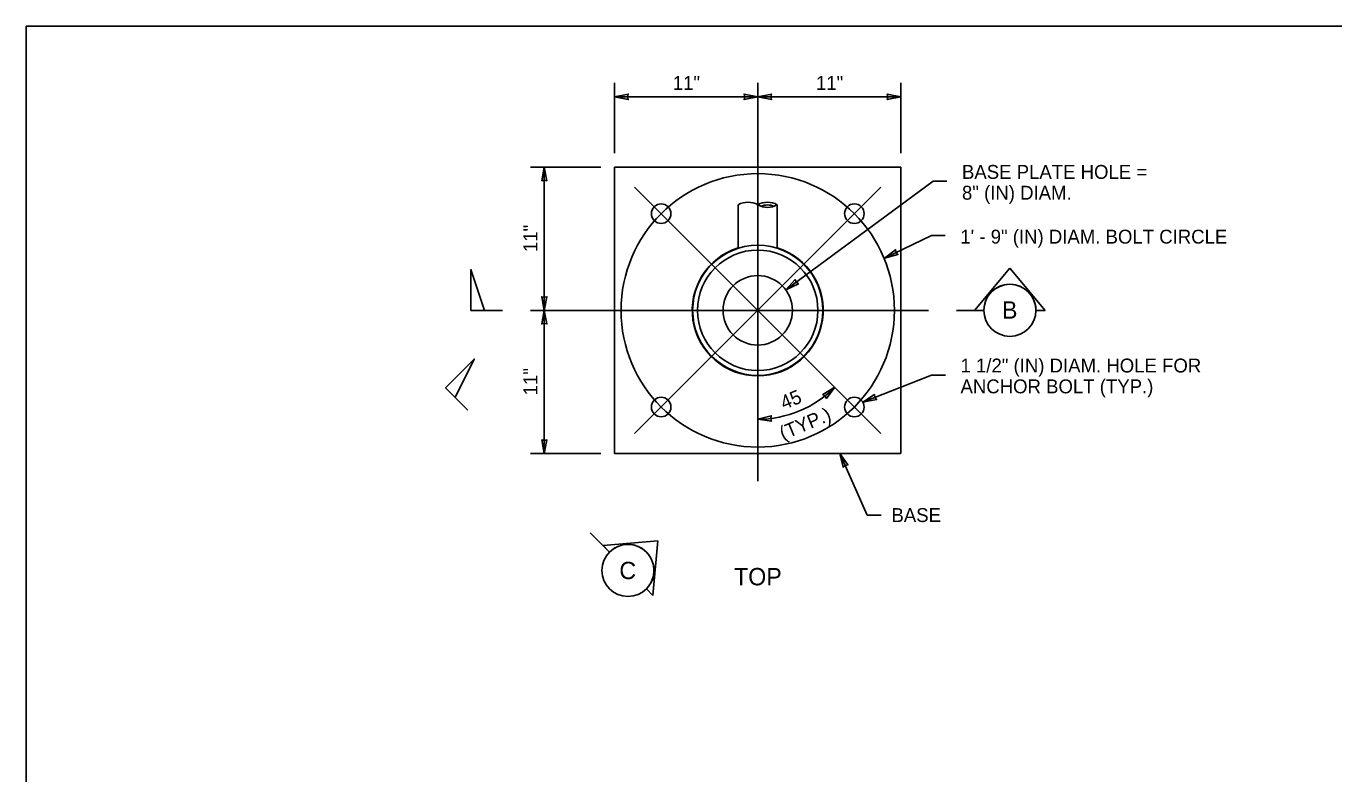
# Model space of a CAD drawing. Extents: x 99862 to 104211, y 98939 to 111076.
# Drawn here: x 100000 to 101507, y 110214 to 111075 of the extents above; entities that cross this region are included whole.
import ezdxf

# ---------------------------------------------------------------- set-up
doc = ezdxf.new("R2010")
doc.units = 0
for name, color, linetype in [('Level 11', 7, 'Continuous'), ('Level 15', 7, 'Continuous'), ('Level 20', 7, 'Continuous'), ('Level 60', 7, 'Continuous'), ('Level 7', 7, 'Continuous'), ('Level 9', 7, 'Continuous')]:
    doc.layers.add(name, color=color, linetype=linetype)

msp = doc.modelspace()

# ---------------------------------------------------------------- linework, layer by layer
at = {"layer": 'Level 11'}
for p, q in [((100820.7, 110869.2), (100820.7, 110819.2)), ((100865.7, 110819.2), (100865.7, 110869.2))]:
    msp.add_line(p, q, dxfattribs=at)
for centre, radius, start, end in [((100832, 110849.7), 22.5, 60, 120), ((100854.5, 110849.7), 22.5, 60, 120), ((100854.5, 110888.7), 22.5, 240, 300), ((100854.5, 110849.7), 19.3, 67.1582, 112.8418)]:
    msp.add_arc(centre, radius, start, end, dxfattribs=at)
at = {"layer": 'Level 15'}
for p, q in [((100678.2, 110928.6), (100678.2, 111009.6)), ((100843.2, 110550.6), (100843.2, 111009.6)), ((101008.2, 110928.6), (101008.2, 111009.6)), ((100843.2, 110993.6), (100678.2, 110993.6)), ((101008.2, 110993.6), (100843.2, 110993.6)), ((100662.2, 110912.6), (100581.2, 110912.6)), ((100597.2, 110912.6), (100597.2, 110747.6)), ((100985.2, 110605.7), (100701.3, 110889.6)), ((100701.3, 110605.7), (100985.2, 110889.6)), ((100875.5, 110771.3), (101045.3, 110896.3)), ((101045.3, 110896.3), (101061.3, 110896.3)), ((100989.3, 110807.7), (101043.4, 110833.7)), ((101043.4, 110833.7), (101059.4, 110833.7)), ((101040.2, 110747.6), (100581.2, 110747.6)), ((100597.2, 110747.6), (100597.2, 110582.6)), ((100964.3, 110641.9), (101043.6, 110673.1)), ((101043.6, 110673.1), (101059.6, 110673.1)), ((100662.2, 110582.6), (100581.2, 110582.6)), ((100937.8, 110582.7), (100969.3, 110511.7)), ((100969.3, 110511.7), (100985.3, 110511.7))]:
    msp.add_line(p, q, dxfattribs=at)
for points in [[(100678.2, 110993.6), (100694, 110990.5), (100693.2, 110993.6), (100694, 110996.7)], [(100843.2, 110993.6), (100827.5, 110990.5), (100828.2, 110993.6), (100827.5, 110996.7)], [(100843.2, 110993.6), (100859, 110990.5), (100858.2, 110993.6), (100859, 110996.7)], [(101008.2, 110993.6), (100992.5, 110990.5), (100993.2, 110993.6), (100992.5, 110996.7)], [(100597.2, 110912.6), (100594.2, 110896.9), (100597.2, 110897.6), (100600.3, 110896.9)], [(100989.3, 110807.7), (101004.7, 110811.9), (101002.7, 110814.3), (101002, 110817.4)], [(100875.5, 110771.3), (100890, 110778.1), (100887.6, 110780.2), (100886.3, 110783.1)], [(100597.2, 110747.6), (100594.2, 110763.3), (100597.2, 110762.6), (100600.3, 110763.3)], [(100597.2, 110747.6), (100594.2, 110731.9), (100597.2, 110732.6), (100600.3, 110731.9)], [(100932, 110658.9), (100922.3, 110646.1), (100920.8, 110648.9), (100918.2, 110650.7)], [(100964.3, 110641.9), (100980.1, 110644.8), (100978.3, 110647.4), (100977.8, 110650.5)], [(100843.2, 110622.1), (100859.1, 110620), (100858.2, 110623), (100858.7, 110626.1)], [(100597.2, 110582.6), (100594.2, 110598.3), (100597.2, 110597.6), (100600.3, 110598.3)], [(100937.8, 110582.7), (100941.5, 110567.1), (100944, 110569), (100947.1, 110569.6)]]:
    msp.add_lwpolyline(points, close=True, dxfattribs=at)
msp.add_circle((100843.2, 110747.6), 157.5, dxfattribs=at)
msp.add_arc((100843.2, 110747.6), 125.5, 270, 315, dxfattribs=at)
at = {"layer": 'Level 60'}
for p, q in [((100000, 111075), (100000, 109000)), ((103150, 111075), (100000, 111075))]:
    msp.add_line(p, q, dxfattribs=at)
at = {"layer": 'Level 7'}
for p, q in [((101008.2, 110912.6), (100678.2, 110912.6)), ((100678.2, 110912.6), (100678.2, 110582.6)), ((101008.2, 110582.6), (101008.2, 110912.6)), ((100678.2, 110582.6), (101008.2, 110582.6))]:
    msp.add_line(p, q, dxfattribs=at)
for centre, radius in [((100731.9, 110859), 11.3), ((100954.6, 110859), 11.3), ((100843.2, 110747.6), 75), ((100843.2, 110747.6), 69.4), ((100843.2, 110747.6), 40), ((100731.9, 110636.2), 11.3), ((100954.6, 110636.2), 11.3)]:
    msp.add_circle(centre, radius, dxfattribs=at)
msp.add_arc((100843.2, 110747.6), 75.5, 107.3457, 72.6543, dxfattribs=at)
at = {"layer": 'Level 9'}
for p, q in [((101133.8, 110796.1), (101093.2, 110747.6)), ((101174.4, 110747.6), (101133.8, 110796.1)), ((100549.2, 110747.6), (100512.7, 110747.6)), ((101102.2, 110747.6), (101072.2, 110747.6)), ((101093.2, 110747.6), (101103.8, 110747.6)), ((101163.8, 110747.6), (101174.4, 110747.6)), ((100509.2, 110632.4), (100483.4, 110658.2)), ((100671.3, 110470.2), (100650.1, 110491.4)), ((100727.9, 110482.2), (100664.9, 110476.6)), ((100722.4, 110419.2), (100727.9, 110482.2)), ((100664.9, 110476.6), (100672.4, 110469.1)), ((100714.9, 110426.7), (100722.4, 110419.2))]:
    msp.add_line(p, q, dxfattribs=at)
for points in [[(100528.2, 110747.6), (100512.7, 110794.5), (100512.7, 110747.6)], [(100494.3, 110647.2), (100516.5, 110691.4), (100483.4, 110658.2)]]:
    msp.add_lwpolyline(points, close=True, dxfattribs=at)
for centre in [(101133.8, 110747.6), (100693.6, 110447.9)]:
    msp.add_circle(centre, 30, dxfattribs=at)
for centre, start, end in [((101133.8, 110747.6), 359.9978, 180.0022), ((100693.6, 110447.9), 314.9978, 135.0022)]:
    msp.add_arc(centre, 30, start, end, dxfattribs=at)

# ---------------------------------------------------------------- texts
at = {"layer": 'Level 15'}
for s, p in [('11"', (100745.3, 111001.6)), ('11"', (100910.3, 111001.6)), ('BASE PLATE HOLE = ', (101078.6, 110899.1)), ('8" (IN) DIAM.', (101078.6, 110875.1)), ('1\' - 9" (IN) DIAM. BOLT CIRCLE', (101076.7, 110824.5)), ('1 1/2" (IN) DIAM. HOLE FOR', (101076.9, 110676)), ('ANCHOR BOLT (TYP.)', (101076.9, 110652))]:
    msp.add_text(s, height=16, dxfattribs=at).set_placement(p)
at = {"layer": 'Level 20'}
for s, rotation, p in [('11"', 90, (100589.2, 110814.7)), ('11"', 90, (100589.2, 110649.7)), ('45', 22.4994, (100873.4, 110632.9)), ('(TYP.)', 22.4994, (100872.3, 110597.8))]:
    msp.add_text(s, height=16, rotation=rotation, dxfattribs=at).set_placement(p)
for s, height, p in [('B', 20, (101124.7, 110738)), ('BASE', 16, (100997.3, 110503.7)), ('C', 20, (100683.7, 110437.9)), ('TOP', 20, (100815.9, 110430.8))]:
    msp.add_text(s, height=height, dxfattribs=at).set_placement(p)

doc.saveas('drawing.dxf')
